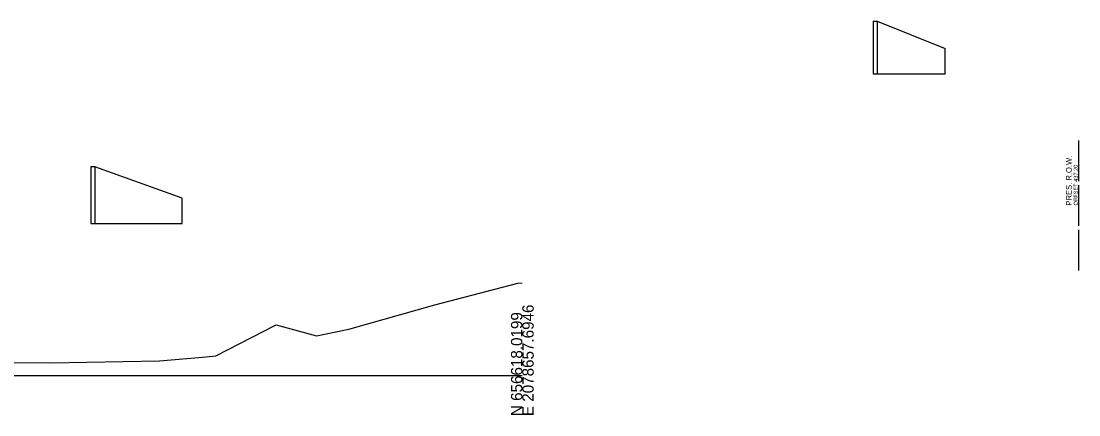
# Model space of a CAD drawing. Extents: x 80 to 2092, y 80 to 1076.
# Drawn here: x 1831.5 to 2092.2, y 909.1 to 1006.1 of the extents above; entities that cross this region are included whole.
import ezdxf

# ---------------------------------------------------------------- set-up
doc = ezdxf.new("R2010")
doc.units = 0
for name, color, linetype in [('DESIGN - DRAINAGE - Cross Drains', 7, 'Continuous'), ('DESIGN - SHEET - Light Grid', 7, 'Continuous'), ('SURVEY - GROUND - Top of Ground', 7, 'Continuous'), ('SURVEY - PROPERTY - ROW Lines', 7, 'Continuous'), ('SURVEY - PROPERTY - ROW Lines Text', 7, 'Continuous')]:
    doc.layers.add(name, color=color, linetype=linetype)

msp = doc.modelspace()

# ---------------------------------------------------------------- linework, layer by layer
at = {"layer": 'DESIGN - DRAINAGE - Cross Drains'}
for p, q in [((2041.49, 1006.13), (2041.49, 993.13)), ((2041.49, 1006.13), (2042.49, 1006.13)), ((2042.49, 1006.13), (2042.49, 993.13)), ((2042.49, 1006.13), (2059.24, 999.38)), ((2059.24, 993.13), (2059.24, 999.38)), ((2041.49, 993.13), (2059.24, 993.13)), ((1848.63, 970.25), (1848.63, 956.25)), ((1849.63, 970.25), (1848.63, 970.25)), ((1849.63, 970.25), (1849.63, 956.25)), ((1871.13, 962.5), (1849.63, 970.25)), ((1871.13, 956.25), (1871.13, 962.5)), ((1848.63, 956.25), (1871.13, 956.25))]:
    msp.add_line(p, q, dxfattribs=at)
at = {"layer": 'DESIGN - SHEET - Light Grid'}
msp.add_line((1655.01, 918.83), (1955.01, 918.83), dxfattribs=at)
at = {"layer": 'SURVEY - GROUND - Top of Ground'}
msp.add_lwpolyline([(1705.6, 921.44), (1709.85, 921.51), (1740.15, 921.43), (1744.38, 921.51), (1775.36, 921.76), (1801.19, 921.9), (1822.13, 922), (1838.71, 921.98), (1865.59, 922.42), (1876.15, 923.37), (1879.45, 923.64), (1894.3, 931.31), (1904.3, 928.59), (1912.26, 930.28), (1933.42, 936.28), (1953.87, 941.54), (1955.01, 941.69)], dxfattribs=at)
at = {"layer": 'SURVEY - PROPERTY - ROW Lines'}
for p, q in [((2092.2, 966.71), (2092.2, 976.71)), ((2092.2, 955.71), (2092.2, 965.71)), ((2092.2, 944.71), (2092.2, 954.71))]:
    msp.add_line(p, q, dxfattribs=at)

# ---------------------------------------------------------------- texts
at = {"layer": 'DESIGN - SHEET - Light Grid'}
for s, p in [('E 2078657.6946', (1957.81, 908.83)), ('N 656618.0199', (1955.01, 908.83))]:
    msp.add_text(s, height=2.8, rotation=90, dxfattribs=at).set_placement(p)
at = {"layer": 'SURVEY - PROPERTY - ROW Lines Text'}
for s, height, p in [('PRES. R.O.W.', 1.4, (2090.45, 960.71)), ('OFFSET 437.20', 1, (2091.95, 960.71))]:
    msp.add_text(s, height=height, rotation=90, dxfattribs=at).set_placement(p)

doc.saveas('drawing.dxf')
